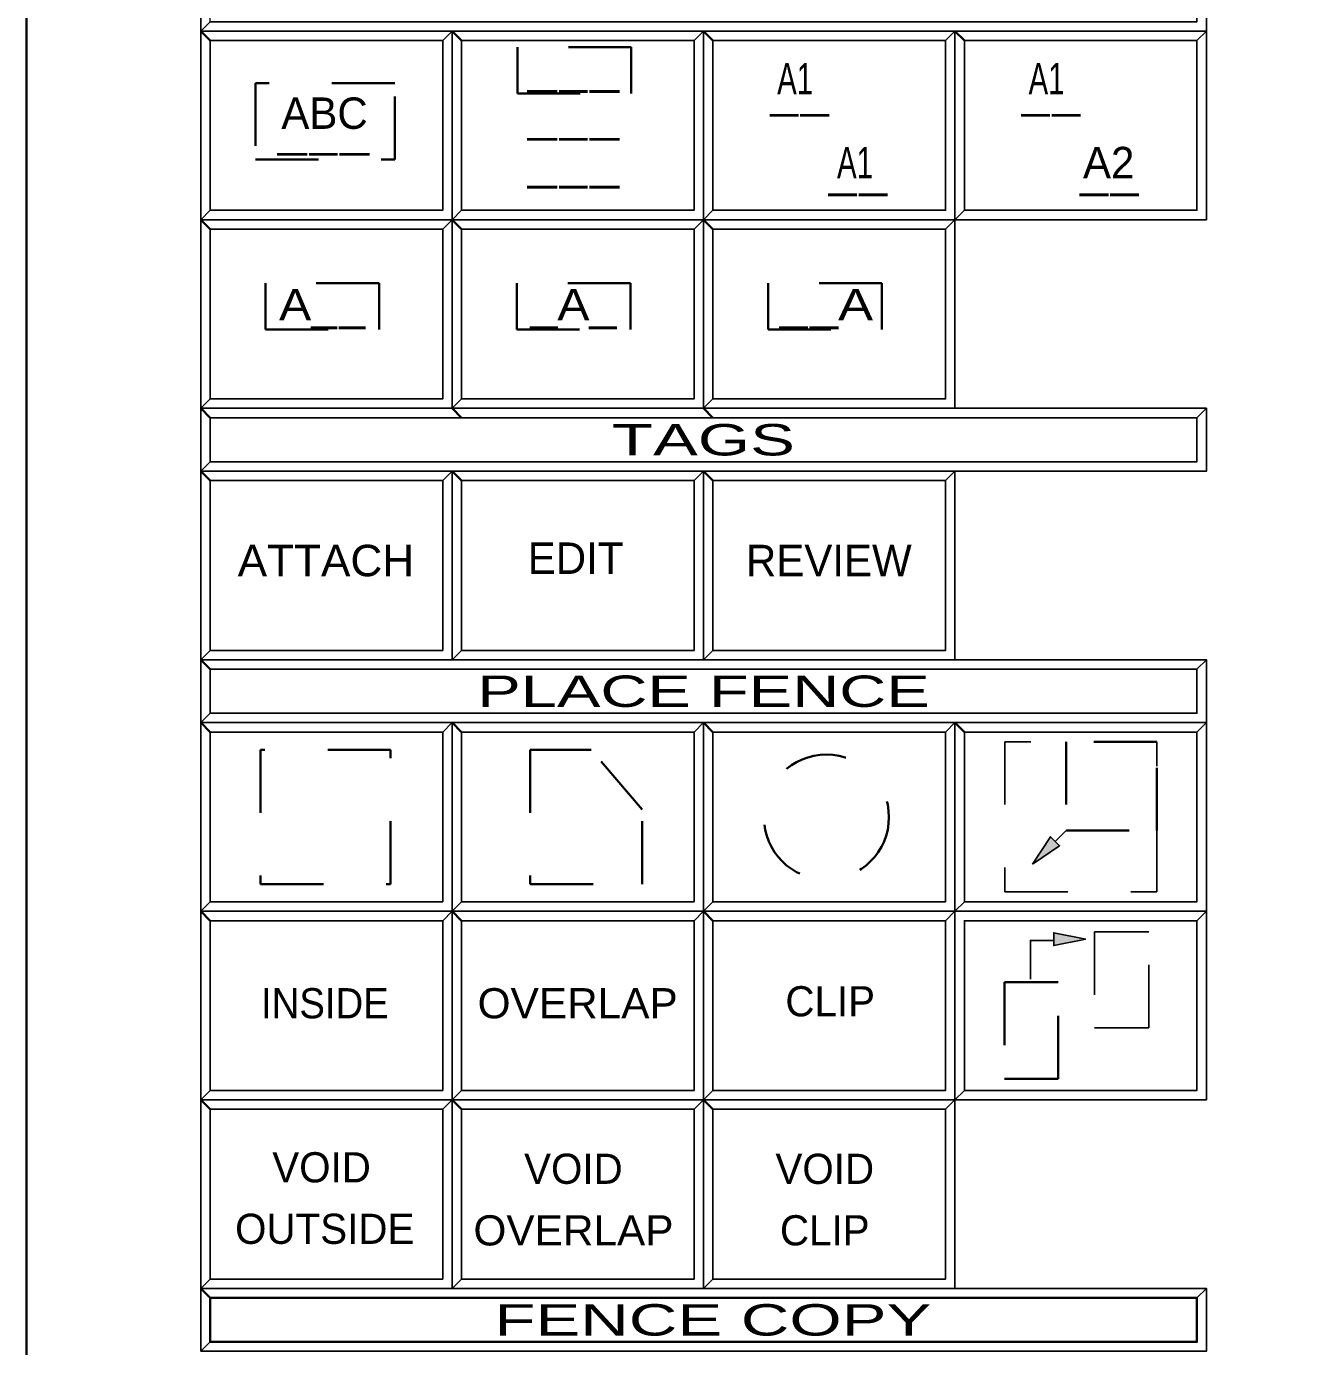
# Model space of a CAD drawing. Extents: x 95906.9 to 95918.9, y 90964.8 to 90972.9.
# Drawn here: x 95906.855 to 95908.882, y 90967.569 to 90969.669 of the extents above; entities that cross this region are included whole.
import ezdxf
from ezdxf.enums import TextEntityAlignment as Align

# ---------------------------------------------------------------- set-up
doc = ezdxf.new("R2010")
doc.units = 0
doc.header["$LTSCALE"] = 0.019
doc.linetypes.add('DOTTED', pattern=[1.5, 0.3, -1.2])
doc.linetypes.add('MEDIUM_DASHED', pattern=[4.5, 3, -1.5])
for name, color, linetype, lineweight in [('1', 7, 'Continuous', 25), ('11', 7, 'Continuous', 25), ('12', 7, 'Continuous', 25), ('18', 7, 'Continuous', 25), ('2', 7, 'Continuous', 13), ('3', 7, 'Continuous', 25), ('4', 7, 'Continuous', 35), ('6', 7, 'Continuous', 35), ('7', 7, 'Continuous', 35)]:
    doc.layers.add(name, color=color, linetype=linetype, lineweight=lineweight)

msp = doc.modelspace()

# ---------------------------------------------------------------- hatches: boundary and pattern name
at = {"layer": '6'}
for points in [[(95908.4558, 90968.3364), (95908.4843, 90968.3801), (95908.4989, 90968.3659)], [(95908.5408, 90968.2173), (95908.4896, 90968.2071), (95908.4896, 90968.2275)]]:
    msp.add_hatch(color=256, dxfattribs=at).paths.add_polyline_path(points)

# ---------------------------------------------------------------- linework, layer by layer
at = {"layer": '1'}
for points in [[(95907.1323, 90969.6617), (95908.7323, 90969.6617), (95908.7323, 90969.7617), (95907.1323, 90969.7617)], [(95907.1323, 90969.3617), (95907.5323, 90969.3617), (95907.5323, 90969.6617), (95907.1323, 90969.6617)], [(95907.5323, 90969.3617), (95907.9323, 90969.3617), (95907.9323, 90969.6617), (95907.5323, 90969.6617)], [(95907.9323, 90969.3617), (95908.3323, 90969.3617), (95908.3323, 90969.6617), (95907.9323, 90969.6617)], [(95908.3323, 90969.3617), (95908.7323, 90969.3617), (95908.7323, 90969.6617), (95908.3323, 90969.6617)], [(95907.1323, 90969.0617), (95907.5323, 90969.0617), (95907.5323, 90969.3617), (95907.1323, 90969.3617)], [(95907.5323, 90969.0617), (95907.9323, 90969.0617), (95907.9323, 90969.3617), (95907.5323, 90969.3617)], [(95907.9323, 90969.0617), (95908.3323, 90969.0617), (95908.3323, 90969.3617), (95907.9323, 90969.3617)], [(95907.1323, 90968.9617), (95908.7323, 90968.9617), (95908.7323, 90969.0617), (95907.1323, 90969.0617)], [(95907.1323, 90968.6617), (95907.5323, 90968.6617), (95907.5323, 90968.9617), (95907.1323, 90968.9617)], [(95907.5323, 90968.6617), (95907.9323, 90968.6617), (95907.9323, 90968.9617), (95907.5323, 90968.9617)], [(95907.9323, 90968.6617), (95908.3323, 90968.6617), (95908.3323, 90968.9617), (95907.9323, 90968.9617)], [(95907.1323, 90968.5617), (95908.7323, 90968.5617), (95908.7323, 90968.6617), (95907.1323, 90968.6617)], [(95907.1323, 90968.2617), (95907.5323, 90968.2617), (95907.5323, 90968.5617), (95907.1323, 90968.5617)], [(95907.5323, 90968.2617), (95907.9323, 90968.2617), (95907.9323, 90968.5617), (95907.5323, 90968.5617)], [(95907.9323, 90968.2617), (95908.3323, 90968.2617), (95908.3323, 90968.5617), (95907.9323, 90968.5617)], [(95908.3323, 90968.2617), (95908.7323, 90968.2617), (95908.7323, 90968.5617), (95908.3323, 90968.5617)], [(95907.1323, 90967.9617), (95907.5323, 90967.9617), (95907.5323, 90968.2617), (95907.1323, 90968.2617)], [(95907.5323, 90967.9617), (95907.9323, 90967.9617), (95907.9323, 90968.2617), (95907.5323, 90968.2617)], [(95907.9323, 90967.9617), (95908.3323, 90967.9617), (95908.3323, 90968.2617), (95907.9323, 90968.2617)], [(95908.3323, 90967.9617), (95908.7323, 90967.9617), (95908.7323, 90968.2617), (95908.3323, 90968.2617)], [(95907.1323, 90967.6617), (95907.5323, 90967.6617), (95907.5323, 90967.9617), (95907.1323, 90967.9617)], [(95907.5323, 90967.6617), (95907.9323, 90967.6617), (95907.9323, 90967.9617), (95907.5323, 90967.9617)], [(95907.9323, 90967.6617), (95908.3323, 90967.6617), (95908.3323, 90967.9617), (95907.9323, 90967.9617)], [(95907.1323, 90967.5617), (95908.7323, 90967.5617), (95908.7323, 90967.6617), (95907.1323, 90967.6617)]]:
    msp.add_lwpolyline(points, close=True, dxfattribs=at)
at = {"layer": '11'}
for points in [[(95907.1473, 90969.3767), (95907.5173, 90969.3767), (95907.5173, 90969.6467), (95907.1473, 90969.6467)], [(95907.5473, 90969.3767), (95907.9173, 90969.3767), (95907.9173, 90969.6467), (95907.5473, 90969.6467)], [(95907.9473, 90969.3767), (95908.3173, 90969.3767), (95908.3173, 90969.6467), (95907.9473, 90969.6467)], [(95908.3473, 90969.3767), (95908.7173, 90969.3767), (95908.7173, 90969.6467), (95908.3473, 90969.6467)], [(95907.1473, 90969.0767), (95907.5173, 90969.0767), (95907.5173, 90969.3467), (95907.1473, 90969.3467)], [(95907.5473, 90969.0767), (95907.9173, 90969.0767), (95907.9173, 90969.3467), (95907.5473, 90969.3467)], [(95907.9473, 90969.0767), (95908.3173, 90969.0767), (95908.3173, 90969.3467), (95907.9473, 90969.3467)], [(95907.1473, 90968.6767), (95907.5173, 90968.6767), (95907.5173, 90968.9467), (95907.1473, 90968.9467)], [(95907.5473, 90968.6767), (95907.9173, 90968.6767), (95907.9173, 90968.9467), (95907.5473, 90968.9467)], [(95907.9473, 90968.6767), (95908.3173, 90968.6767), (95908.3173, 90968.9467), (95907.9473, 90968.9467)], [(95907.1473, 90968.2767), (95907.5173, 90968.2767), (95907.5173, 90968.5467), (95907.1473, 90968.5467)], [(95907.5473, 90968.2767), (95907.9173, 90968.2767), (95907.9173, 90968.5467), (95907.5473, 90968.5467)], [(95907.9473, 90968.2767), (95908.3173, 90968.2767), (95908.3173, 90968.5467), (95907.9473, 90968.5467)], [(95908.3473, 90968.2767), (95908.7173, 90968.2767), (95908.7173, 90968.5467), (95908.3473, 90968.5467)], [(95907.1473, 90967.9767), (95907.5173, 90967.9767), (95907.5173, 90968.2467), (95907.1473, 90968.2467)], [(95907.5473, 90967.9767), (95907.9173, 90967.9767), (95907.9173, 90968.2467), (95907.5473, 90968.2467)], [(95907.9473, 90967.9767), (95908.3173, 90967.9767), (95908.3173, 90968.2467), (95907.9473, 90968.2467)], [(95908.3473, 90967.9767), (95908.7173, 90967.9767), (95908.7173, 90968.2467), (95908.3473, 90968.2467)], [(95907.1473, 90967.6767), (95907.5173, 90967.6767), (95907.5173, 90967.9467), (95907.1473, 90967.9467)], [(95907.5473, 90967.6767), (95907.9173, 90967.6767), (95907.9173, 90967.9467), (95907.5473, 90967.9467)], [(95907.9473, 90967.6767), (95908.3173, 90967.6767), (95908.3173, 90967.9467), (95907.9473, 90967.9467)]]:
    msp.add_lwpolyline(points, close=True, dxfattribs=at)
at = {"layer": '12'}
for points in [[(95907.1473, 90969.3767), (95907.5173, 90969.3767), (95907.5173, 90969.6467), (95907.1473, 90969.6467)], [(95907.1473, 90968.6767), (95907.5173, 90968.6767), (95907.5173, 90968.9467), (95907.1473, 90968.9467)], [(95907.5473, 90968.6767), (95907.9173, 90968.6767), (95907.9173, 90968.9467), (95907.5473, 90968.9467)], [(95907.9473, 90968.6767), (95908.3173, 90968.6767), (95908.3173, 90968.9467), (95907.9473, 90968.9467)], [(95907.1473, 90968.2767), (95907.5173, 90968.2767), (95907.5173, 90968.5467), (95907.1473, 90968.5467)]]:
    msp.add_lwpolyline(points, close=True, dxfattribs=at)
at = {"layer": '18'}
for points in [[(95907.1473, 90968.9767), (95908.7173, 90968.9767), (95908.7173, 90969.0467), (95907.1473, 90969.0467)], [(95907.1473, 90968.5767), (95908.7173, 90968.5767), (95908.7173, 90968.6467), (95907.1473, 90968.6467)]]:
    msp.add_lwpolyline(points, close=True, dxfattribs=at)
at = {"layer": '18', "lineweight": 35}
msp.add_lwpolyline([(95907.1473, 90967.5767), (95908.7173, 90967.5767), (95908.7173, 90967.6467), (95907.1473, 90967.6467)], close=True, dxfattribs=at)
at = {"layer": '2'}
for points in [[(95907.1323, 90969.7617), (95907.1323, 90969.6617), (95907.1473, 90969.6767), (95907.1473, 90969.7467), (95908.7173, 90969.7467), (95908.7323, 90969.7617)], [(95907.1323, 90969.6617), (95907.1323, 90969.3617), (95907.1473, 90969.3767), (95907.1473, 90969.6467), (95907.5173, 90969.6467), (95907.5323, 90969.6617)], [(95907.5323, 90969.6617), (95907.5323, 90969.3617), (95907.5473, 90969.3767), (95907.5473, 90969.6467), (95907.9173, 90969.6467), (95907.9323, 90969.6617)], [(95907.9323, 90969.6617), (95907.9323, 90969.3617), (95907.9473, 90969.3767), (95907.9473, 90969.6467), (95908.3173, 90969.6467), (95908.3323, 90969.6617)], [(95908.3323, 90969.6617), (95908.3323, 90969.3617), (95908.3473, 90969.3767), (95908.3473, 90969.6467), (95908.7173, 90969.6467), (95908.7323, 90969.6617)], [(95907.1323, 90969.3617), (95907.1323, 90969.0617), (95907.1473, 90969.0767), (95907.1473, 90969.3467), (95907.5173, 90969.3467), (95907.5323, 90969.3617)], [(95907.5323, 90969.3617), (95907.5323, 90969.0617), (95907.5473, 90969.0767), (95907.5473, 90969.3467), (95907.9173, 90969.3467), (95907.9323, 90969.3617)], [(95907.9323, 90969.3617), (95907.9323, 90969.0617), (95907.9473, 90969.0767), (95907.9473, 90969.3467), (95908.3173, 90969.3467), (95908.3323, 90969.3617)], [(95907.1323, 90969.0617), (95907.1323, 90968.9617), (95907.1473, 90968.9767), (95907.1473, 90969.0467), (95908.7173, 90969.0467), (95908.7323, 90969.0617)], [(95907.1323, 90968.9617), (95907.1323, 90968.6617), (95907.1473, 90968.6767), (95907.1473, 90968.9467), (95907.5173, 90968.9467), (95907.5323, 90968.9617)], [(95907.5323, 90968.9617), (95907.5323, 90968.6617), (95907.5473, 90968.6767), (95907.5473, 90968.9467), (95907.9173, 90968.9467), (95907.9323, 90968.9617)], [(95907.9323, 90968.9617), (95907.9323, 90968.6617), (95907.9473, 90968.6767), (95907.9473, 90968.9467), (95908.3173, 90968.9467), (95908.3323, 90968.9617)], [(95907.1323, 90968.6617), (95907.1323, 90968.5617), (95907.1473, 90968.5767), (95907.1473, 90968.6467), (95908.7173, 90968.6467), (95908.7323, 90968.6617)], [(95907.1323, 90968.5617), (95907.1323, 90968.2617), (95907.1473, 90968.2767), (95907.1473, 90968.5467), (95907.5173, 90968.5467), (95907.5323, 90968.5617)], [(95907.5323, 90968.5617), (95907.5323, 90968.2617), (95907.5473, 90968.2767), (95907.5473, 90968.5467), (95907.9173, 90968.5467), (95907.9323, 90968.5617)], [(95907.9323, 90968.5617), (95907.9323, 90968.2617), (95907.9473, 90968.2767), (95907.9473, 90968.5467), (95908.3173, 90968.5467), (95908.3323, 90968.5617)], [(95908.3323, 90968.5617), (95908.3323, 90968.2617), (95908.3473, 90968.2767), (95908.3473, 90968.5467), (95908.7173, 90968.5467), (95908.7323, 90968.5617)], [(95907.1323, 90968.2617), (95907.1323, 90967.9617), (95907.1473, 90967.9767), (95907.1473, 90968.2467), (95907.5173, 90968.2467), (95907.5323, 90968.2617)], [(95907.5323, 90968.2617), (95907.5323, 90967.9617), (95907.5473, 90967.9767), (95907.5473, 90968.2467), (95907.9173, 90968.2467), (95907.9323, 90968.2617)], [(95907.9323, 90968.2617), (95907.9323, 90967.9617), (95907.9473, 90967.9767), (95907.9473, 90968.2467), (95908.3173, 90968.2467), (95908.3323, 90968.2617)], [(95908.3323, 90968.2617), (95908.3323, 90967.9617), (95908.3473, 90967.9767), (95908.3473, 90968.2467), (95908.7173, 90968.2467), (95908.7323, 90968.2617)], [(95907.1323, 90967.9617), (95907.1323, 90967.6617), (95907.1473, 90967.6767), (95907.1473, 90967.9467), (95907.5173, 90967.9467), (95907.5323, 90967.9617)], [(95907.5323, 90967.9617), (95907.5323, 90967.6617), (95907.5473, 90967.6767), (95907.5473, 90967.9467), (95907.9173, 90967.9467), (95907.9323, 90967.9617)], [(95907.9323, 90967.9617), (95907.9323, 90967.6617), (95907.9473, 90967.6767), (95907.9473, 90967.9467), (95908.3173, 90967.9467), (95908.3323, 90967.9617)], [(95907.1323, 90967.6617), (95907.1323, 90967.5617), (95907.1473, 90967.5767), (95907.1473, 90967.6467), (95908.7173, 90967.6467), (95908.7323, 90967.6617)]]:
    msp.add_lwpolyline(points, close=True, dxfattribs=at)
at = {"layer": '3'}
for points in [[(95907.1323, 90969.6617), (95908.7323, 90969.6617), (95908.7323, 90969.7617), (95908.7173, 90969.7467), (95908.7173, 90969.6767), (95907.1473, 90969.6767)], [(95907.1323, 90969.3617), (95907.5323, 90969.3617), (95907.5323, 90969.6617), (95907.5173, 90969.6467), (95907.5173, 90969.3767), (95907.1473, 90969.3767)], [(95907.5323, 90969.3617), (95907.9323, 90969.3617), (95907.9323, 90969.6617), (95907.9173, 90969.6467), (95907.9173, 90969.3767), (95907.5473, 90969.3767)], [(95907.9323, 90969.3617), (95908.3323, 90969.3617), (95908.3323, 90969.6617), (95908.3173, 90969.6467), (95908.3173, 90969.3767), (95907.9473, 90969.3767)], [(95908.3323, 90969.3617), (95908.7323, 90969.3617), (95908.7323, 90969.6617), (95908.7173, 90969.6467), (95908.7173, 90969.3767), (95908.3473, 90969.3767)], [(95907.1323, 90969.0617), (95907.5323, 90969.0617), (95907.5323, 90969.3617), (95907.5173, 90969.3467), (95907.5173, 90969.0767), (95907.1473, 90969.0767)], [(95907.5323, 90969.0617), (95907.9323, 90969.0617), (95907.9323, 90969.3617), (95907.9173, 90969.3467), (95907.9173, 90969.0767), (95907.5473, 90969.0767)], [(95907.9323, 90969.0617), (95908.3323, 90969.0617), (95908.3323, 90969.3617), (95908.3173, 90969.3467), (95908.3173, 90969.0767), (95907.9473, 90969.0767)], [(95907.1323, 90968.9617), (95908.7323, 90968.9617), (95908.7323, 90969.0617), (95908.7173, 90969.0467), (95908.7173, 90968.9767), (95907.1473, 90968.9767)], [(95907.1323, 90968.6617), (95907.5323, 90968.6617), (95907.5323, 90968.9617), (95907.5173, 90968.9467), (95907.5173, 90968.6767), (95907.1473, 90968.6767)], [(95907.5323, 90968.6617), (95907.9323, 90968.6617), (95907.9323, 90968.9617), (95907.9173, 90968.9467), (95907.9173, 90968.6767), (95907.5473, 90968.6767)], [(95907.9323, 90968.6617), (95908.3323, 90968.6617), (95908.3323, 90968.9617), (95908.3173, 90968.9467), (95908.3173, 90968.6767), (95907.9473, 90968.6767)], [(95907.1323, 90968.5617), (95908.7323, 90968.5617), (95908.7323, 90968.6617), (95908.7173, 90968.6467), (95908.7173, 90968.5767), (95907.1473, 90968.5767)], [(95907.1323, 90968.2617), (95907.5323, 90968.2617), (95907.5323, 90968.5617), (95907.5173, 90968.5467), (95907.5173, 90968.2767), (95907.1473, 90968.2767)], [(95907.5323, 90968.2617), (95907.9323, 90968.2617), (95907.9323, 90968.5617), (95907.9173, 90968.5467), (95907.9173, 90968.2767), (95907.5473, 90968.2767)], [(95907.9323, 90968.2617), (95908.3323, 90968.2617), (95908.3323, 90968.5617), (95908.3173, 90968.5467), (95908.3173, 90968.2767), (95907.9473, 90968.2767)], [(95908.3323, 90968.2617), (95908.7323, 90968.2617), (95908.7323, 90968.5617), (95908.7173, 90968.5467), (95908.7173, 90968.2767), (95908.3473, 90968.2767)], [(95907.1323, 90967.9617), (95907.5323, 90967.9617), (95907.5323, 90968.2617), (95907.5173, 90968.2467), (95907.5173, 90967.9767), (95907.1473, 90967.9767)], [(95907.5323, 90967.9617), (95907.9323, 90967.9617), (95907.9323, 90968.2617), (95907.9173, 90968.2467), (95907.9173, 90967.9767), (95907.5473, 90967.9767)], [(95907.9323, 90967.9617), (95908.3323, 90967.9617), (95908.3323, 90968.2617), (95908.3173, 90968.2467), (95908.3173, 90967.9767), (95907.9473, 90967.9767)], [(95908.3323, 90967.9617), (95908.7323, 90967.9617), (95908.7323, 90968.2617), (95908.7173, 90968.2467), (95908.7173, 90967.9767), (95908.3473, 90967.9767)], [(95907.1323, 90967.6617), (95907.5323, 90967.6617), (95907.5323, 90967.9617), (95907.5173, 90967.9467), (95907.5173, 90967.6767), (95907.1473, 90967.6767)], [(95907.5323, 90967.6617), (95907.9323, 90967.6617), (95907.9323, 90967.9617), (95907.9173, 90967.9467), (95907.9173, 90967.6767), (95907.5473, 90967.6767)], [(95907.9323, 90967.6617), (95908.3323, 90967.6617), (95908.3323, 90967.9617), (95908.3173, 90967.9467), (95908.3173, 90967.6767), (95907.9473, 90967.6767)], [(95907.1323, 90967.5617), (95908.7323, 90967.5617), (95908.7323, 90967.6617), (95908.7173, 90967.6467), (95908.7173, 90967.5767), (95907.1473, 90967.5767)]]:
    msp.add_lwpolyline(points, close=True, dxfattribs=at)
at = {"layer": '4'}
for p, q in [((95907.1473, 90969.6467), (95907.1323, 90969.6617)), ((95907.5473, 90969.6467), (95907.5323, 90969.6617)), ((95907.9473, 90969.6467), (95907.9323, 90969.6617)), ((95908.3473, 90969.6467), (95908.3323, 90969.6617)), ((95907.1473, 90969.3467), (95907.1323, 90969.3617)), ((95907.1473, 90969.3467), (95907.1323, 90969.3617)), ((95907.5473, 90969.3467), (95907.5323, 90969.3617)), ((95907.5473, 90969.3467), (95907.5323, 90969.3617)), ((95907.9473, 90969.3467), (95907.9323, 90969.3617)), ((95907.9473, 90969.3467), (95907.9323, 90969.3617)), ((95907.1473, 90969.0467), (95907.1323, 90969.0617)), ((95907.5473, 90969.0467), (95907.5323, 90969.0617)), ((95907.9473, 90969.0467), (95907.9323, 90969.0617)), ((95907.1473, 90968.9467), (95907.1323, 90968.9617)), ((95907.5473, 90968.9467), (95907.5323, 90968.9617)), ((95907.9473, 90968.9467), (95907.9323, 90968.9617)), ((95907.1473, 90968.6467), (95907.1323, 90968.6617)), ((95907.1473, 90968.5467), (95907.1323, 90968.5617)), ((95907.5473, 90968.5467), (95907.5323, 90968.5617)), ((95907.9473, 90968.5467), (95907.9323, 90968.5617)), ((95908.3473, 90968.5467), (95908.3323, 90968.5617)), ((95907.1473, 90968.2467), (95907.1323, 90968.2617)), ((95907.5473, 90968.2467), (95907.5323, 90968.2617)), ((95907.9473, 90968.2467), (95907.9323, 90968.2617)), ((95907.1473, 90967.9467), (95907.1323, 90967.9617)), ((95907.5473, 90967.9467), (95907.5323, 90967.9617)), ((95907.9473, 90967.9467), (95907.9323, 90967.9617)), ((95907.1473, 90967.6467), (95907.1323, 90967.6617))]:
    msp.add_line(p, q, dxfattribs=at)
at = {"layer": '6', "lineweight": 25}
msp.add_line((95908.5093, 90968.3899), (95908.4919, 90968.3725), dxfattribs=at)
at = {"layer": '6', "linetype": 'MEDIUM_DASHED'}
for points in [[(95907.6362, 90969.5625), (95907.8173, 90969.5625), (95907.8173, 90969.6363), (95907.6362, 90969.6363)], [(95907.2194, 90969.4576), (95907.4409, 90969.4576), (95907.4409, 90969.5791), (95907.2194, 90969.5791)], [(95907.235, 90969.187), (95907.4161, 90969.187), (95907.4161, 90969.2608), (95907.235, 90969.2608)], [(95907.635, 90969.187), (95907.8161, 90969.187), (95907.8161, 90969.2608), (95907.635, 90969.2608)], [(95908.035, 90969.187), (95908.2161, 90969.187), (95908.2161, 90969.2608), (95908.035, 90969.2608)]]:
    msp.add_lwpolyline(points, close=True, dxfattribs=at)
at = {"layer": '6', "linetype": 'DOTTED'}
for points in [[(95907.2274, 90968.305), (95907.4344, 90968.305), (95907.4344, 90968.5184), (95907.2274, 90968.5184)], [(95907.6564, 90968.305), (95907.8344, 90968.305), (95907.8344, 90968.4236), (95907.7536, 90968.5184), (95907.6564, 90968.5184)], [(95908.6533, 90968.5313), (95908.5093, 90968.5313), (95908.5093, 90968.3899), (95908.6533, 90968.3899)], [(95908.4112, 90967.9951), (95908.4964, 90967.9951), (95908.4964, 90968.1487), (95908.4112, 90968.1487)]]:
    msp.add_lwpolyline(points, close=True, dxfattribs=at)
at = {"layer": '6', "linetype": 'MEDIUM_DASHED', "lineweight": 25}
for points in [[(95908.4119, 90968.2925), (95908.6533, 90968.2925), (95908.6533, 90968.5313), (95908.4119, 90968.5313)], [(95908.5545, 90968.0764), (95908.6409, 90968.0764), (95908.6409, 90968.2287), (95908.5545, 90968.2287)]]:
    msp.add_lwpolyline(points, close=True, dxfattribs=at)
at = {"layer": '6', "lineweight": 25}
for points in [[(95908.4558, 90968.3364), (95908.4843, 90968.3801), (95908.4989, 90968.3659)], [(95908.5408, 90968.2173), (95908.4896, 90968.2071), (95908.4896, 90968.2275)]]:
    msp.add_lwpolyline(points, close=True, dxfattribs=at)
msp.add_lwpolyline([(95908.4523, 90968.1538), (95908.4523, 90968.2154), (95908.4896, 90968.2154)], dxfattribs=at)
at = {"layer": '6', "linetype": 'DOTTED'}
msp.add_circle((95908.1278, 90968.4115), 0.0995, dxfattribs=at)
at = {"layer": '7'}
msp.add_lwpolyline([(95906.8548, 90972.8617), (95918.8548, 90972.8617), (95918.8548, 90964.7617), (95906.8548, 90964.7617)], close=True, dxfattribs=at)

# ---------------------------------------------------------------- texts
at = {"layer": '6'}
for s, height, width, p in [('A1', 0.04999, 0.7, (95908.078, 90969.561)), ('A1', 0.04999, 0.7, (95908.4781, 90969.561)), ('___', 0.04999, 1.3, (95907.7253, 90969.5779)), ('__', 0.04999, 1.25, (95908.085, 90969.5398)), ('__', 0.04999, 1.25, (95908.485, 90969.5398)), ('___', 0.04999, 1.3, (95907.7253, 90969.5017)), ('___', 0.04999, 1.3, (95907.3274, 90969.4779)), ('A1', 0.04999, 0.7, (95908.1733, 90969.4276)), ('___', 0.04999, 1.3, (95907.7253, 90969.4255)), ('__', 0.04999, 1.25, (95908.1779, 90969.4136)), ('__', 0.04999, 1.25, (95908.5779, 90969.4136)), ('A__', 0.04999, 1.15, (95907.3252, 90969.2017)), ('_A_', 0.04999, 1.15, (95907.7252, 90969.2017)), ('__A', 0.04999, 1.25, (95908.1277, 90969.2017)), ('ATTACH', 0.05, 1.05, (95907.3314, 90968.7946)), ('INSIDE', 0.048, 0.95, (95907.3298, 90968.0914)), ('OVERLAP', 0.048, 1.05, (95907.732, 90968.0914)), ('OVERLAP', 0.048, 1.05, (95907.7253, 90967.7301))]:
    msp.add_text(s, height=height, dxfattribs=dict(at, width=width)).set_placement(p, align=Align.CENTER)
for s, height, p in [('ABC', 0.04999, (95907.3292, 90969.5062)), ('A2', 0.04999, (95908.5769, 90969.4276)), ('EDIT', 0.05, (95907.7287, 90968.7983)), ('REVIEW', 0.05, (95908.1316, 90968.7946)), ('CLIP', 0.048, (95908.1338, 90968.0945)), ('VOID', 0.048, (95907.3245, 90967.8304)), ('VOID', 0.048, (95907.7252, 90967.8281)), ('VOID', 0.048, (95908.1252, 90967.828)), ('OUTSIDE', 0.048, (95907.3295, 90967.7326)), ('CLIP', 0.048, (95908.1252, 90967.7302))]:
    msp.add_text(s, height=height, dxfattribs=at).set_placement(p, align=Align.CENTER)
at = {"layer": '7'}
for s, height, width, p in [('      TAGS      ', 0.05, 1.6, (95907.9321, 90968.9867)), ('      PLACE FENCE      ', 0.04999, 1.55, (95907.9322, 90968.5867)), ('       FENCE COPY      ', 0.04999, 1.6, (95907.9322, 90967.5867))]:
    msp.add_text(s, height=height, dxfattribs=dict(at, width=width)).set_placement(p, align=Align.CENTER)

doc.saveas('drawing.dxf')
